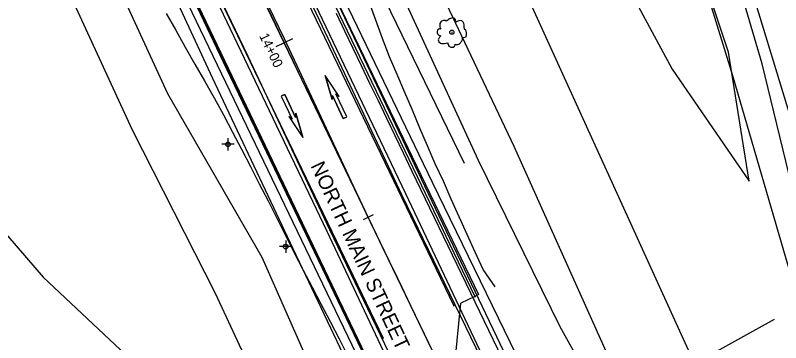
# Model space of a CAD drawing. Extents: x 1040814 to 1041501, y 1126274 to 1127077.
# Drawn here: x 1041044.8 to 1041242.1, y 1126776.9 to 1126861.4 of the extents above; entities that cross this region are included whole.
import ezdxf

# ---------------------------------------------------------------- set-up
doc = ezdxf.new("R2010")
doc.units = 0
for name, color, linetype in [('AC_P', 7, 'Continuous'), ('ACSR_P_T', 7, 'Continuous'), ('ACSRT_P', 7, 'Continuous'), ('LABL', 7, 'Continuous'), ('LAM', 7, 'Continuous'), ('LELB', 7, 'Continuous'), ('LFILL_P', 7, 'Continuous'), ('LTD', 7, 'Continuous'), ('MHB', 7, 'Continuous'), ('O_Details_Text Title and Subtitle Proposed_P_T', 7, 'Continuous'), ('PE', 7, 'Continuous'), ('PE_P', 7, 'Continuous'), ('PET_P', 7, 'Continuous'), ('PSCL_P', 7, 'Continuous'), ('PSU', 7, 'Continuous'), ('RBS_P', 7, 'Continuous'), ('RGB_P', 7, 'Continuous'), ('RGC', 7, 'Continuous'), ('S', 7, 'Continuous'), ('STFBY', 7, 'Continuous'), ('STFBY_P', 7, 'Continuous'), ('STSEW', 7, 'Continuous'), ('STSEY_P_T', 7, 'Continuous'), ('UEO', 7, 'Continuous'), ('UPGW', 7, 'Continuous')]:
    doc.layers.add(name, color=color, linetype=linetype)

msp = doc.modelspace()

# ---------------------------------------------------------------- linework, layer by layer
at = {"layer": 'AC_P'}
msp.add_line((1041101.89, 1126879.82), (1041218.17, 1126637.8), dxfattribs=at)
at = {"layer": 'ACSRT_P'}
for points in [[(1041116.3, 1126855.38), (1041111.97, 1126853.31)], [(1041137.08, 1126809.9), (1041134.49, 1126808.65)]]:
    msp.add_lwpolyline(points, dxfattribs=at)
at = {"layer": 'LABL'}
msp.add_lwpolyline([(1041251.99, 1126646.31), (1041228.46, 1126690.65), (1041209.42, 1126737.58), (1041185.31, 1126781.06), (1041164.2, 1126823.95), (1041143.23, 1126869.63), (1041121.91, 1126913.97), (1041100.61, 1126958.66)], dxfattribs=at)
at = {"layer": 'LAM'}
for points in [[(1041254.78, 1126777.09), (1041237.34, 1126848.88), (1041223.61, 1126895.73), (1041224.21, 1126946.09), (1041205.17, 1127008.43)], [(1041178.07, 1126995.53), (1041184.35, 1126983.26), (1041193.48, 1126948.75), (1041202.81, 1126927.03), (1041215.34, 1126892.52), (1041229.72, 1126845.87), (1041245.84, 1126790.43)]]:
    msp.add_lwpolyline(points, dxfattribs=at)
at = {"layer": 'LELB'}
for points in [[(1041146.07, 1126980.3), (1041167.77, 1126934.56), (1041192.01, 1126888.74), (1041214.15, 1126847.53), (1041233.99, 1126818.61), (1041228.67, 1126851.95), (1041212.83, 1126899.47), (1041200.3, 1126938.77), (1041181.33, 1126991.97), (1041179.68, 1126996.3)], [(1041095.55, 1126956.25), (1041116.17, 1126912.13), (1041138.6, 1126868.47), (1041160.54, 1126823.31)], [(1041041.98, 1126930.75), (1041063.24, 1126886.6), (1041084.03, 1126841.27), (1041108.41, 1126799.02), (1041128.47, 1126753.39), (1041143.12, 1126720.8)], [(1041123.26, 1126726.85), (1041116.78, 1126745.76), (1041096.43, 1126789.68), (1041075.03, 1126831.81), (1041051.47, 1126883.04), (1041030.52, 1126925.29)], [(1041244.14, 1126655.64), (1041235.67, 1126692.06), (1041212.68, 1126740.02), (1041173.42, 1126827.61), (1041152.07, 1126872.82), (1041141.9, 1126894.54)], [(1041035.89, 1126812.55), (1041051.97, 1126793.82)], [(1041051.97, 1126793.82), (1041123.26, 1126726.85)]]:
    msp.add_lwpolyline(points, dxfattribs=at)
at = {"layer": 'LFILL_P'}
for points in [[(1041168.5, 1126791.39), (1041165.46, 1126795.8), (1041163.37, 1126800.34), (1041161.29, 1126804.89), (1041159.24, 1126809.45), (1041157.21, 1126814.02), (1041155.19, 1126818.6), (1041153.06, 1126823.12), (1041151.1, 1126827.73), (1041149.14, 1126832.34), (1041147.18, 1126836.94), (1041145.2, 1126841.54), (1041143.24, 1126846.14), (1041141.29, 1126850.75), (1041139.44, 1126855.41), (1041137.75, 1126860.14), (1041136.08, 1126864.89)], [(1041083.73, 1126861.93), (1041086.18, 1126857.56), (1041088.64, 1126853.19), (1041091.11, 1126848.83), (1041093.6, 1126844.48), (1041096.1, 1126840.14), (1041098.52, 1126835.75), (1041100.84, 1126831.31), (1041103.14, 1126826.88), (1041105.43, 1126822.43), (1041107.71, 1126817.97), (1041109.97, 1126813.51), (1041112.21, 1126809.05), (1041114.44, 1126804.57), (1041116.69, 1126800.1), (1041119.04, 1126795.68), (1041121.37, 1126791.26), (1041123.69, 1126786.83), (1041126, 1126782.39), (1041128.29, 1126777.94), (1041130.76, 1126773.09)]]:
    msp.add_lwpolyline(points, dxfattribs=at)
at = {"layer": 'LTD'}
for points in [[(1041160.95, 1126857.66), (1041160.68, 1126857.76), (1041160.59, 1126857.88), (1041160.62, 1126857.97), (1041160.56, 1126858.39), (1041160.56, 1126858.95), (1041160.44, 1126859.34), (1041160.29, 1126859.65), (1041159.93, 1126860.01), (1041159.66, 1126860.07), (1041159.13, 1126860.01), (1041158.92, 1126859.95), (1041158.52, 1126859.74), (1041158.46, 1126859.71), (1041158.4, 1126859.92), (1041158.34, 1126860.25), (1041158.13, 1126860.55), (1041157.92, 1126860.7), (1041157.74, 1126860.79), (1041157.49, 1126860.79), (1041157.31, 1126860.7), (1041157.01, 1126860.61), (1041156.77, 1126860.55), (1041156.47, 1126860.37), (1041156.32, 1126860.19), (1041155.88, 1126859.92), (1041155.66, 1126860.1), (1041155.24, 1126860.1), (1041154.73, 1126859.92), (1041154.52, 1126859.77), (1041154.3, 1126859.3), (1041154.24, 1126858.84), (1041154.24, 1126858.42), (1041154.36, 1126858.12), (1041154.52, 1126857.88)], [(1041154.52, 1126857.88), (1041154.06, 1126857.94), (1041153.7, 1126857.63), (1041153.58, 1126857.24), (1041153.58, 1126856.94), (1041153.7, 1126856.64), (1041154.03, 1126856.3), (1041154.27, 1126856.18), (1041154.49, 1126856.12), (1041154.33, 1126855.94), (1041154.21, 1126855.76), (1041153.85, 1126855.11), (1041153.97, 1126854.57), (1041154.43, 1126854.2), (1041154.73, 1126854.17), (1041155.36, 1126854.17), (1041155.91, 1126854.2), (1041156.32, 1126854.32), (1041156.32, 1126854.11), (1041156.47, 1126853.69), (1041156.59, 1126853.48), (1041156.77, 1126853.36), (1041157.1, 1126853.24), (1041157.52, 1126853.21), (1041157.74, 1126853.24), (1041158.04, 1126853.42), (1041158.19, 1126853.81), (1041158.22, 1126853.96), (1041158.4, 1126853.93), (1041158.82, 1126853.87), (1041159.19, 1126853.96), (1041159.31, 1126854.05), (1041159.61, 1126854.35), (1041159.7, 1126854.48), (1041159.93, 1126854.75), (1041160.05, 1126854.93), (1041160.14, 1126855.26), (1041160.11, 1126855.7), (1041160.32, 1126855.73), (1041161.07, 1126855.89)], [(1041157.42, 1126857.06), (1041157.42, 1126857.06), (1041157.42, 1126857.06), (1041157.42, 1126857.08), (1041157.42, 1126857.08), (1041157.42, 1126857.08), (1041157.42, 1126857.09), (1041157.4, 1126857.09), (1041157.4, 1126857.09), (1041157.4, 1126857.09), (1041157.4, 1126857.09), (1041157.4, 1126857.11), (1041157.39, 1126857.11), (1041157.39, 1126857.11), (1041157.39, 1126857.11), (1041157.37, 1126857.11), (1041157.37, 1126857.11), (1041157.37, 1126857.11), (1041157.36, 1126857.11), (1041157.36, 1126857.11), (1041157.36, 1126857.11), (1041157.34, 1126857.11), (1041157.34, 1126857.09), (1041157.34, 1126857.09), (1041157.34, 1126857.09), (1041157.33, 1126857.09), (1041157.33, 1126857.09), (1041157.33, 1126857.08), (1041157.33, 1126857.08), (1041157.33, 1126857.08), (1041157.33, 1126857.06), (1041157.33, 1126857.06), (1041157.33, 1126857.06), (1041157.33, 1126857.05), (1041157.33, 1126857.05), (1041157.33, 1126857.05), (1041157.33, 1126857.03), (1041157.33, 1126857.03), (1041157.34, 1126857.03), (1041157.34, 1126857.03), (1041157.34, 1126857.02), (1041157.34, 1126857.02), (1041157.36, 1126857.02), (1041157.36, 1126857.02), (1041157.36, 1126857.02), (1041157.37, 1126857.02), (1041157.37, 1126857.02), (1041157.37, 1126857.02), (1041157.39, 1126857.02), (1041157.39, 1126857.02), (1041157.39, 1126857.02), (1041157.4, 1126857.02), (1041157.4, 1126857.02), (1041157.4, 1126857.03), (1041157.4, 1126857.03), (1041157.4, 1126857.03), (1041157.42, 1126857.03), (1041157.42, 1126857.05), (1041157.42, 1126857.05), (1041157.42, 1126857.05), (1041157.42, 1126857.06)], [(1041161.07, 1126855.89), (1041161.11, 1126856.46), (1041161.11, 1126856.94), (1041161.05, 1126857.36), (1041160.95, 1126857.66)]]:
    msp.add_lwpolyline(points, dxfattribs=at)
msp.add_circle((1041157.37, 1126857.06), 0.533, dxfattribs=at)
at = {"layer": 'MHB'}
msp.add_lwpolyline([(1041273.77, 1126564.22), (1041288, 1126693.29), (1041193.5, 1127002.88)], dxfattribs=at)
at = {"layer": 'O_Details_Text Title and Subtitle Proposed_P_T'}
for p, q in [((1041126.52, 1126839.66), (1041124.72, 1126845.88)), ((1041128.34, 1126840.5), (1041124.72, 1126845.88)), ((1041113.85, 1126840.8), (1041113.82, 1126840.79)), ((1041113.86, 1126840.78), (1041113.83, 1126840.77)), ((1041127.46, 1126841.2), (1041128.34, 1126840.5)), ((1041115.31, 1126835.3), (1041118.93, 1126829.93)), ((1041116.19, 1126834.61), (1041115.31, 1126835.3)), ((1041117.12, 1126836.15), (1041118.93, 1126829.93)), ((1041129.79, 1126835.02), (1041129.82, 1126835.04)), ((1041129.8, 1126835.01), (1041129.83, 1126835.02))]:
    msp.add_line(p, q, dxfattribs=at)
at = {"layer": 'PE'}
for points in [[(1041081.62, 1126949.62), (1041102.41, 1126905.66), (1041123.97, 1126860.46), (1041145.4, 1126815.4), (1041166.83, 1126770.22), (1041188.29, 1126725.66), (1041210.14, 1126680.18), (1041231.44, 1126635.95), (1041253.25, 1126591), (1041274.98, 1126546.22), (1041296.15, 1126500.9), (1041317.55, 1126455.84), (1041318.73, 1126453.38)], [(1041061.22, 1126939.91), (1041082.3, 1126895.54), (1041103.78, 1126850.36), (1041125.11, 1126805.74), (1041146.56, 1126760.22), (1041167.95, 1126715.79), (1041189.67, 1126670.72), (1041211.13, 1126626.27), (1041232.46, 1126581.39), (1041245.23, 1126553.4), (1041244.27, 1126543.82), (1041238.51, 1126536.54)]]:
    msp.add_lwpolyline(points, dxfattribs=at)
at = {"layer": 'PE_P'}
for points in [[(1041085.39, 1126951.41), (1041087.54, 1126946.9), (1041089.69, 1126942.39), (1041091.84, 1126937.88), (1041093.99, 1126933.37), (1041096.14, 1126928.87), (1041098.3, 1126924.36), (1041100.45, 1126919.85), (1041102.61, 1126915.34), (1041104.76, 1126910.84), (1041106.92, 1126906.33), (1041109.08, 1126901.83), (1041111.24, 1126897.32), (1041113.4, 1126892.82), (1041115.56, 1126888.31), (1041163.24, 1126789.08), (1041163.39, 1126788.72)], [(1041056.5, 1126937.66), (1041058.65, 1126933.14), (1041060.8, 1126928.63), (1041062.95, 1126924.11), (1041065.11, 1126919.59), (1041067.27, 1126915.08), (1041069.42, 1126910.56), (1041071.58, 1126906.05), (1041073.74, 1126901.53), (1041075.9, 1126897.02), (1041078.06, 1126892.51), (1041080.22, 1126887.99), (1041082.39, 1126883.48), (1041084.55, 1126878.97), (1041086.72, 1126874.46), (1041134.52, 1126774.96), (1041134.93, 1126774.41)]]:
    msp.add_lwpolyline(points, dxfattribs=at)
at = {"layer": 'PET_P'}
for points in [[(1041079.97, 1126948.84), (1041082.12, 1126944.32), (1041084.27, 1126939.81), (1041086.42, 1126935.3), (1041088.57, 1126930.79), (1041090.73, 1126926.28), (1041092.88, 1126921.77), (1041095.04, 1126917.26), (1041097.19, 1126912.75), (1041099.35, 1126908.25), (1041101.51, 1126903.74), (1041103.67, 1126899.23), (1041105.83, 1126894.73), (1041107.99, 1126890.22), (1041110.16, 1126885.72), (1041157.77, 1126786.61), (1041157.87, 1126786.37)], [(1041061.92, 1126940.24), (1041064.07, 1126935.72), (1041066.22, 1126931.21), (1041068.37, 1126926.69), (1041070.52, 1126922.18), (1041072.68, 1126917.66), (1041074.84, 1126913.15), (1041076.99, 1126908.63), (1041079.15, 1126904.12), (1041081.31, 1126899.61), (1041083.47, 1126895.1), (1041085.63, 1126890.59), (1041087.8, 1126886.08), (1041089.96, 1126881.57), (1041092.13, 1126877.06), (1041139.68, 1126778.08), (1041139.75, 1126777.99)]]:
    msp.add_lwpolyline(points, dxfattribs=at)
at = {"layer": 'PSCL_P'}
for p in [(1041163.32, 1126788.89), (1041157.44, 1126764.21)]:
    msp.add_line(p, (1041159.71, 1126787.16), dxfattribs=at)
at = {"layer": 'PSU'}
for points in [[(1041271.9, 1126563.2), (1041257.91, 1126593.44), (1041235.69, 1126638.05), (1041214.95, 1126682.34), (1041193.32, 1126727.74), (1041171.68, 1126772.68), (1041150.4, 1126817.33), (1041128.89, 1126862.55), (1041107.28, 1126907.69), (1041105.25, 1126911.9)], [(1041075.19, 1126898.29), (1041078.06, 1126892.31), (1041099.27, 1126847.58), (1041120.87, 1126802.65), (1041142.35, 1126757.81), (1041163.59, 1126712.68), (1041185.79, 1126668.17), (1041209.73, 1126624.25), (1041231.42, 1126579.4), (1041240.95, 1126552.57), (1041242.07, 1126544.47), (1041234.49, 1126537.64), (1041227.67, 1126534.18), (1041227.86, 1126530.17)]]:
    msp.add_lwpolyline(points, dxfattribs=at)
at = {"layer": 'RBS_P'}
for points in [[(1041086.29, 1126951.84), (1041086.3, 1126951.84), (1041088.44, 1126947.33), (1041090.59, 1126942.82), (1041092.74, 1126938.31), (1041094.9, 1126933.8), (1041097.05, 1126929.29), (1041099.2, 1126924.78), (1041101.36, 1126920.27), (1041103.51, 1126915.77), (1041105.67, 1126911.26), (1041107.83, 1126906.75), (1041109.99, 1126902.25), (1041112.15, 1126897.74), (1041114.31, 1126893.24), (1041116.47, 1126888.74), (1041164.26, 1126789.35), (1041163.32, 1126788.89)], [(1041054.69, 1126936.8), (1041056.84, 1126932.29), (1041058.99, 1126927.78), (1041061.14, 1126923.26), (1041063.3, 1126918.74), (1041065.45, 1126914.23), (1041067.61, 1126909.71), (1041069.77, 1126905.2), (1041071.93, 1126900.68), (1041074.09, 1126896.17), (1041076.25, 1126891.66), (1041078.41, 1126887.14), (1041080.58, 1126882.63), (1041082.74, 1126878.12), (1041084.91, 1126873.61), (1041132.71, 1126774.11), (1041134.48, 1126775.04)]]:
    msp.add_lwpolyline(points, dxfattribs=at)
at = {"layer": 'RGB_P'}
for points in [[(1041056.73, 1126937.77), (1041147.4, 1126748)], [(1041127.55, 1126861.96), (1041129.7, 1126857.45), (1041131.86, 1126852.94), (1041134.01, 1126848.44), (1041136.17, 1126843.93), (1041138.33, 1126839.43), (1041140.49, 1126834.92), (1041142.65, 1126830.42), (1041144.81, 1126825.92), (1041146.97, 1126821.41), (1041174.93, 1126763.22)]]:
    msp.add_lwpolyline(points, dxfattribs=at)
at = {"layer": 'RGC'}
for points in [[(1041087.65, 1126952.49), (1041108.77, 1126908.46), (1041130.6, 1126863.31), (1041152.26, 1126818.34), (1041173.96, 1126773.83), (1041196.71, 1126728.83)], [(1041150.76, 1126727.14), (1041138.24, 1126755.14), (1041116.46, 1126801.14), (1041095.64, 1126845.33), (1041074.27, 1126891.55), (1041053.63, 1126936.29)]]:
    msp.add_lwpolyline(points, dxfattribs=at)
at = {"layer": 'S'}
for p, q in [((1041099.63, 1126829.71), (1041099.63, 1126826.56)), ((1041101.21, 1126828.13), (1041098.06, 1126828.13)), ((1041116.11, 1126801.75), (1041112.96, 1126801.75)), ((1041114.53, 1126803.32), (1041114.53, 1126800.17))]:
    msp.add_line(p, q, dxfattribs=at)
for centre in [(1041099.63, 1126828.13), (1041114.53, 1126801.75)]:
    msp.add_circle(centre, 0.591, dxfattribs=at)
at = {"layer": 'STFBY'}
msp.add_lwpolyline([(1041071.47, 1126944.79), (1041092.31, 1126900.59), (1041114.11, 1126855.47), (1041135.17, 1126810.47), (1041156.8, 1126765.46), (1041178.14, 1126720.76), (1041199.95, 1126675.44), (1041221.33, 1126630.97), (1041242.89, 1126586.34), (1041262.65, 1126544.69)], dxfattribs=at)
at = {"layer": 'STFBY_P'}
msp.add_lwpolyline([(1041109.8, 1126863.36), (1041111.97, 1126858.85), (1041114.13, 1126854.34), (1041116.3, 1126849.84), (1041118.46, 1126845.33), (1041120.63, 1126840.82), (1041122.79, 1126836.32), (1041124.96, 1126831.81), (1041127.12, 1126827.3), (1041129.29, 1126822.8), (1041131.45, 1126818.29), (1041133.62, 1126813.78), (1041135.79, 1126809.28), (1041137.95, 1126804.77), (1041140.12, 1126800.26), (1041142.28, 1126795.76), (1041144.45, 1126791.25), (1041146.61, 1126786.74), (1041148.78, 1126782.24), (1041150.94, 1126777.73), (1041153.11, 1126773.22)], dxfattribs=at)
at = {"layer": 'STSEW'}
for points in [[(1041080.88, 1126949.27), (1041101.64, 1126905.36), (1041123.25, 1126860.06), (1041144.5, 1126815.03), (1041166.26, 1126769.97), (1041187.32, 1126725.16), (1041209.31, 1126679.76), (1041230.58, 1126635.5), (1041252.28, 1126590.51), (1041273.68, 1126545.52), (1041295.33, 1126500.52), (1041316.59, 1126455.37), (1041317.78, 1126452.92)], [(1041062.04, 1126940.3), (1041083.12, 1126896.06), (1041104.75, 1126850.88), (1041125.82, 1126806.14), (1041147.63, 1126760.76), (1041168.87, 1126716.25), (1041190.63, 1126671.14), (1041211.99, 1126626.71), (1041233.6, 1126581.88), (1041249.19, 1126549.07)]]:
    msp.add_lwpolyline(points, dxfattribs=at)
at = {"layer": 'STSEY_P_T'}
for p, q in [((1041128.34, 1126840.5), (1041124.72, 1126845.88)), ((1041124.72, 1126845.88), (1041126.52, 1126839.66)), ((1041114.3, 1126841.01), (1041113.4, 1126840.59)), ((1041113.4, 1126840.59), (1041116.19, 1126834.61)), ((1041113.4, 1126840.59), (1041116.19, 1126834.61)), ((1041114.3, 1126841.01), (1041117.09, 1126835.03)), ((1041117.09, 1126835.03), (1041114.3, 1126841.01)), ((1041126.55, 1126840.77), (1041126.52, 1126839.66)), ((1041126.52, 1126839.66), (1041126.55, 1126840.77)), ((1041129.35, 1126834.79), (1041126.55, 1126840.77)), ((1041126.55, 1126840.77), (1041129.35, 1126834.79)), ((1041130.25, 1126835.22), (1041127.46, 1126841.2)), ((1041130.25, 1126835.22), (1041127.46, 1126841.2)), ((1041127.46, 1126841.2), (1041128.34, 1126840.5)), ((1041116.19, 1126834.61), (1041115.31, 1126835.3)), ((1041115.31, 1126835.3), (1041118.93, 1126829.93)), ((1041117.09, 1126835.03), (1041117.12, 1126836.15)), ((1041117.12, 1126836.15), (1041117.09, 1126835.03)), ((1041118.93, 1126829.93), (1041117.12, 1126836.15)), ((1041129.35, 1126834.79), (1041130.25, 1126835.22))]:
    msp.add_line(p, q, dxfattribs=at)
for points in [[(1041114.3, 1126841.01), (1041113.85, 1126840.8), (1041113.4, 1126840.59)], [(1041129.35, 1126834.79), (1041129.8, 1126835.01), (1041130.25, 1126835.22)]]:
    msp.add_lwpolyline(points, dxfattribs=at)
at = {"layer": 'UEO'}
msp.add_lwpolyline([(1041152.19, 1126920.49), (1041219.1, 1126773.21)], dxfattribs=at)
at = {"layer": 'UPGW'}
msp.add_lwpolyline([(1041240.44, 1126782.91), (1041221.54, 1126772.41)], dxfattribs=at)

# ---------------------------------------------------------------- texts
at = {"layer": 'ACSR_P_T'}
msp.add_text('14+00', height=2.496, rotation=295.6611, dxfattribs=at).set_placement((1041107.64, 1126856.11))
at = {"layer": 'O_Details_Text Title and Subtitle Proposed_P_T'}
msp.add_text('NORTH MAIN STREET', height=3.7536, rotation=295.0387, dxfattribs=at).set_placement((1041120.85, 1126822.62))

doc.saveas('drawing.dxf')
